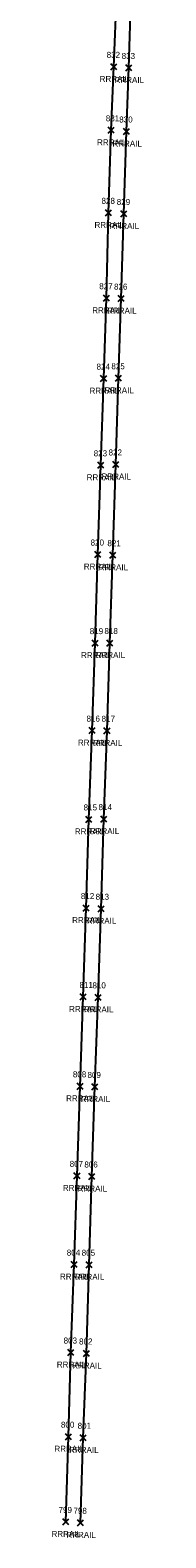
# Model space of a CAD drawing. Extents: x 1715662 to 1717487, y 887396 to 890004.
# Drawn here: x 1716436 to 1716467, y 887396 to 887898 of the extents above; entities that cross this region are included whole.
import ezdxf

# ---------------------------------------------------------------- set-up
doc = ezdxf.new("R2010")
doc.units = 0
for name, color, linetype in [('R_A', 7, 'Continuous'), ('R_I', 7, 'Continuous'), ('R_TIC', 7, 'Continuous'), ('RR', 7, 'Continuous')]:
    doc.layers.add(name, color=color, linetype=linetype)

msp = doc.modelspace()

# ---------------------------------------------------------------- linework, layer by layer
at = {"layer": 'R_TIC'}
for points in [[(1716455.99, 887884.76), (1716457.99, 887886.76)], [(1716457.99, 887884.76), (1716455.99, 887886.76)], [(1716460.97, 887884.39), (1716462.97, 887886.39)], [(1716462.97, 887884.39), (1716460.97, 887886.39)], [(1716455.13, 887863.63), (1716457.13, 887865.63)], [(1716457.13, 887863.63), (1716455.13, 887865.63)], [(1716460.25, 887863.23), (1716462.25, 887865.23)], [(1716462.25, 887863.23), (1716460.25, 887865.23)], [(1716454.26, 887836.15), (1716456.26, 887838.15)], [(1716456.26, 887836.15), (1716454.26, 887838.15)], [(1716459.35, 887835.78), (1716461.35, 887837.78)], [(1716461.35, 887835.78), (1716459.35, 887837.78)], [(1716453.51, 887807.71), (1716455.51, 887809.71)], [(1716455.51, 887807.71), (1716453.51, 887809.71)], [(1716458.49, 887807.58), (1716460.49, 887809.58)], [(1716460.49, 887807.58), (1716458.49, 887809.58)], [(1716452.62, 887780.94), (1716454.62, 887782.94)], [(1716454.62, 887780.94), (1716452.62, 887782.94)], [(1716457.56, 887781.07), (1716459.56, 887783.07)], [(1716459.56, 887781.07), (1716457.56, 887783.07)], [(1716451.67, 887752.08), (1716453.67, 887754.08)], [(1716453.67, 887752.08), (1716451.67, 887754.08)], [(1716456.63, 887752.36), (1716458.63, 887754.36)], [(1716458.63, 887752.36), (1716456.63, 887754.36)], [(1716450.72, 887722.38), (1716452.72, 887724.38)], [(1716452.72, 887722.38), (1716450.72, 887724.38)], [(1716455.66, 887722.15), (1716457.66, 887724.15)], [(1716457.66, 887722.15), (1716455.66, 887724.15)], [(1716449.81, 887692.87), (1716451.81, 887694.87)], [(1716451.81, 887692.87), (1716449.81, 887694.87)], [(1716454.68, 887692.91), (1716456.68, 887694.91)], [(1716456.68, 887692.91), (1716454.68, 887694.91)], [(1716448.76, 887663.74), (1716450.76, 887665.74)], [(1716450.76, 887663.74), (1716448.76, 887665.74)], [(1716453.73, 887663.67), (1716455.73, 887665.67)], [(1716455.73, 887663.67), (1716453.73, 887665.67)], [(1716447.73, 887634.17), (1716449.73, 887636.17)], [(1716449.73, 887634.17), (1716447.73, 887636.17)], [(1716452.72, 887634.27), (1716454.72, 887636.27)], [(1716454.72, 887634.27), (1716452.72, 887636.27)], [(1716446.84, 887604.66), (1716448.84, 887606.66)], [(1716448.84, 887604.66), (1716446.84, 887606.66)], [(1716451.75, 887604.41), (1716453.75, 887606.41)], [(1716453.75, 887604.41), (1716451.75, 887606.41)], [(1716445.81, 887575.05), (1716447.81, 887577.05)], [(1716447.81, 887575.05), (1716445.81, 887577.05)], [(1716450.78, 887574.91), (1716452.78, 887576.91)], [(1716452.78, 887574.91), (1716450.78, 887576.91)], [(1716444.82, 887545.3), (1716446.82, 887547.3)], [(1716446.82, 887545.3), (1716444.82, 887547.3)], [(1716449.69, 887545.09), (1716451.69, 887547.09)], [(1716451.69, 887545.09), (1716449.69, 887547.09)], [(1716443.74, 887515.48), (1716445.74, 887517.48)], [(1716445.74, 887515.48), (1716443.74, 887517.48)], [(1716448.69, 887515.27), (1716450.69, 887517.27)], [(1716450.69, 887515.27), (1716448.69, 887517.27)], [(1716442.78, 887485.94), (1716444.78, 887487.94)], [(1716444.78, 887485.94), (1716442.78, 887487.94)], [(1716447.74, 887485.88), (1716449.74, 887487.88)], [(1716449.74, 887485.88), (1716447.74, 887487.88)], [(1716441.73, 887456.66), (1716443.73, 887458.66)], [(1716443.73, 887456.66), (1716441.73, 887458.66)], [(1716446.86, 887456.34), (1716448.86, 887458.34)], [(1716448.86, 887456.34), (1716446.86, 887458.34)], [(1716440.93, 887428.63), (1716442.93, 887430.63)], [(1716442.93, 887428.63), (1716440.93, 887430.63)], [(1716445.83, 887428.26), (1716447.83, 887430.26)], [(1716447.83, 887428.26), (1716445.83, 887430.26)], [(1716439.97, 887400.26), (1716441.97, 887402.26)], [(1716441.97, 887400.26), (1716439.97, 887402.26)], [(1716444.92, 887399.96), (1716446.92, 887401.96)], [(1716446.92, 887399.96), (1716444.92, 887401.96)]]:
    msp.add_lwpolyline(points, dxfattribs=at)
at = {"layer": 'RR'}
for points in [[(1716440.97, 887401.26), (1716441.93, 887429.63), (1716442.73, 887457.66), (1716443.78, 887486.94), (1716444.74, 887516.48), (1716445.82, 887546.3), (1716446.81, 887576.05), (1716447.84, 887605.66), (1716448.73, 887635.17), (1716449.76, 887664.74), (1716450.81, 887693.87), (1716451.72, 887723.38), (1716452.67, 887753.08), (1716453.62, 887781.94), (1716454.51, 887808.71), (1716455.26, 887837.15), (1716456.13, 887864.63), (1716456.99, 887885.76), (1716457.98, 887910.49), (1716459.38, 887957.61), (1716460.39, 887983.06)], [(1716445.92, 887400.96), (1716446.83, 887429.26), (1716447.86, 887457.34), (1716448.74, 887486.88), (1716449.69, 887516.27), (1716450.69, 887546.09), (1716451.78, 887575.91), (1716452.75, 887605.41), (1716453.72, 887635.27), (1716454.73, 887664.67), (1716455.68, 887693.91), (1716456.66, 887723.15), (1716457.63, 887753.36), (1716458.56, 887782.07), (1716459.49, 887808.58), (1716460.35, 887836.78), (1716461.25, 887864.23), (1716461.97, 887885.39), (1716462.83, 887910.17)]]:
    msp.add_lwpolyline(points, dxfattribs=at)

# ---------------------------------------------------------------- texts
at = {"layer": 'R_A'}
for p in [(1716452.28, 887880.76), (1716457.26, 887880.39), (1716451.42, 887859.63), (1716456.54, 887859.23), (1716450.56, 887832.15), (1716455.64, 887831.78), (1716449.81, 887803.71), (1716454.78, 887803.58), (1716448.91, 887776.94), (1716453.85, 887777.07), (1716447.96, 887748.08), (1716452.92, 887748.36), (1716447.01, 887718.38), (1716451.95, 887718.15), (1716446.1, 887688.87), (1716450.97, 887688.91), (1716445.05, 887659.74), (1716450.02, 887659.67), (1716444.03, 887630.17), (1716449.01, 887630.27), (1716443.13, 887600.66), (1716448.04, 887600.41), (1716442.1, 887571.05), (1716447.07, 887570.91), (1716441.11, 887541.3), (1716445.98, 887541.09), (1716440.03, 887511.48), (1716444.98, 887511.27), (1716439.07, 887481.94), (1716444.03, 887481.88), (1716438.02, 887452.66), (1716443.15, 887452.34), (1716437.22, 887424.63), (1716442.12, 887424.26), (1716436.26, 887396.26), (1716441.21, 887395.96)]:
    msp.add_text('RRRAIL', height=2, dxfattribs=at).set_placement(p)
at = {"layer": 'R_I'}
for s, p in [('832', (1716454.62, 887888.76)), ('833', (1716459.61, 887888.39)), ('831', (1716454.34, 887867.63)), ('830', (1716458.8, 887867.23)), ('828', (1716452.9, 887840.15)), ('829', (1716457.98, 887839.78)), ('827', (1716452.15, 887811.71)), ('826', (1716457.07, 887811.58)), ('824', (1716451.25, 887784.94)), ('825', (1716456.19, 887785.07)), ('823', (1716450.3, 887756.08)), ('822', (1716455.26, 887756.36)), ('820', (1716449.27, 887726.38)), ('821', (1716454.87, 887726.15)), ('819', (1716449, 887696.87)), ('818', (1716453.88, 887696.91)), ('816', (1716447.91, 887667.74)), ('817', (1716452.93, 887667.67)), ('815', (1716446.94, 887638.17)), ('814', (1716451.92, 887638.27)), ('812', (1716446.04, 887608.66)), ('813', (1716450.95, 887608.41)), ('811', (1716445.58, 887579.05)), ('810', (1716449.89, 887578.91)), ('808', (1716443.38, 887549.3)), ('809', (1716448.24, 887549.09)), ('807', (1716442.3, 887519.48)), ('806', (1716447.19, 887519.27)), ('804', (1716441.34, 887489.94)), ('805', (1716446.3, 887489.88)), ('803', (1716440.29, 887460.66)), ('802', (1716445.42, 887460.34)), ('800', (1716439.4, 887432.63)), ('801', (1716444.95, 887432.26)), ('799', (1716438.6, 887404.26)), ('798', (1716443.55, 887403.96))]:
    msp.add_text(s, height=2, dxfattribs=at).set_placement(p)

doc.saveas('drawing.dxf')
